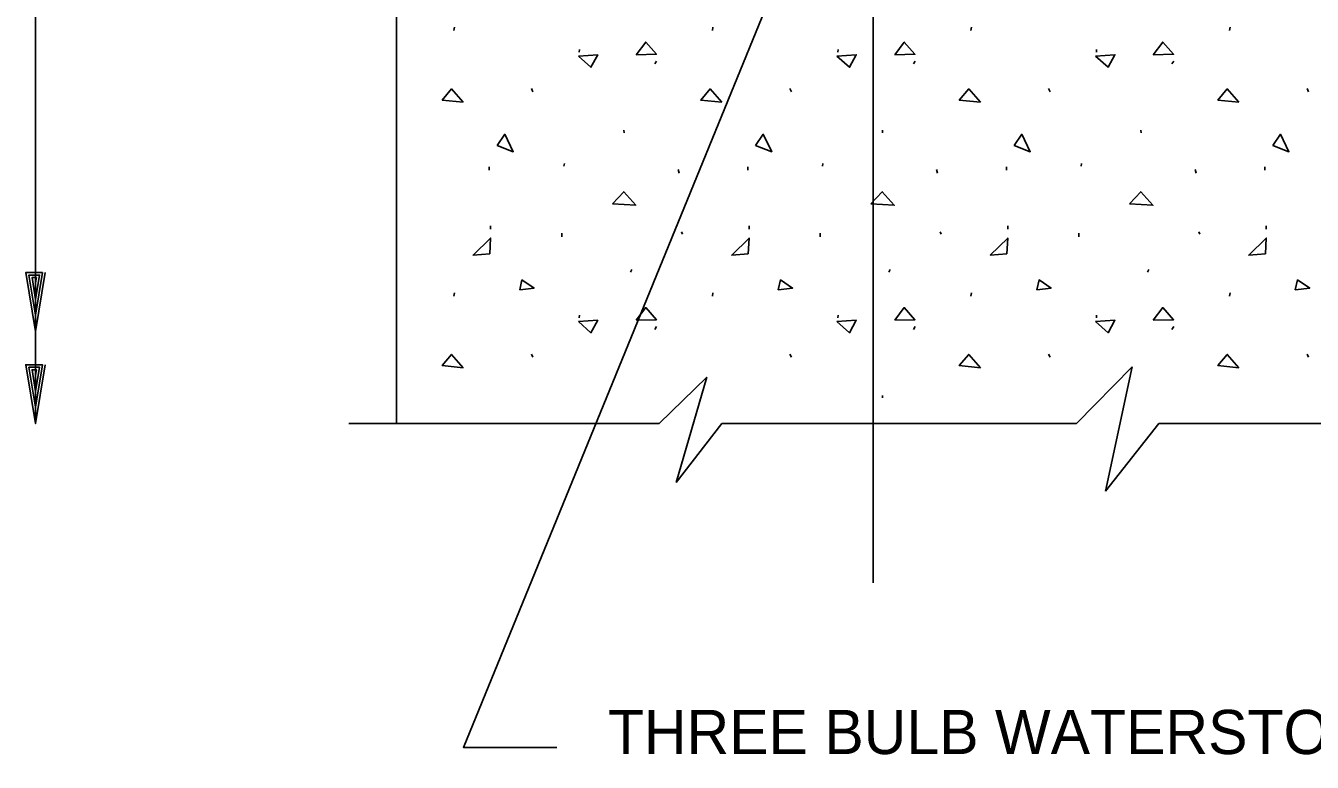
# Model space of a CAD drawing. Extents: x 44743.44 to 44747.1, y 44738.46 to 44741.29.
# Drawn here: x 44745.0695 to 44745.4095, y 44739.0153 to 44739.2099 of the extents above; entities that cross this region are included whole.
import ezdxf

# ---------------------------------------------------------------- set-up
doc = ezdxf.new("R2010")
doc.units = 0
for name, color, linetype in [('Level 1', 7, 'Continuous'), ('Level 10', 7, 'Continuous'), ('Level 2', 7, 'Continuous'), ('Level 8', 7, 'Continuous'), ('S-ANNO-TEXT', 7, 'Continuous')]:
    doc.layers.add(name, color=color, linetype=linetype)

msp = doc.modelspace()

# ---------------------------------------------------------------- linework, layer by layer
at = {"layer": 'Level 1'}
for p, q in [((44745.29347, 44739.69833), (44745.29347, 44739.06275)), ((44745.07206, 44739.10476), (44745.07206, 44739.35544)), ((44745.06947, 44739.14467), (44745.06947, 44739.14467)), ((44745.07389, 44739.14467), (44745.07389, 44739.14467)), ((44745.07464, 44739.14467), (44745.07464, 44739.14467)), ((44745.07031, 44739.14401), (44745.07031, 44739.14401)), ((44745.07114, 44739.14334), (44745.07114, 44739.14334)), ((44745.07206, 44739.14192), (44745.07206, 44739.14192)), ((44745.07231, 44739.14334), (44745.07231, 44739.14334)), ((44745.07314, 44739.14401), (44745.07314, 44739.14401)), ((44745.23686, 44739.10476), (44745.2495, 44739.11704)), ((44745.2495, 44739.11704), (44745.24135, 44739.08919)), ((44745.34716, 44739.10476), (44745.36187, 44739.1198)), ((44745.36187, 44739.1198), (44745.35486, 44739.08694)), ((44745.07206, 44739.10909), (44745.07206, 44739.10909)), ((44745.07206, 44739.10476), (44745.07206, 44739.10476)), ((44745.15487, 44739.10476), (44745.23686, 44739.10476)), ((44745.24135, 44739.08919), (44745.25345, 44739.10476)), ((44745.25345, 44739.10476), (44745.34716, 44739.10476)), ((44745.35486, 44739.08694), (44745.36897, 44739.10476)), ((44745.36897, 44739.10476), (44745.43132, 44739.10476))]:
    msp.add_line(p, q, dxfattribs=at)
for points in [[(44745.07464, 44739.14467), (44745.07206, 44739.12909), (44745.06947, 44739.14467), (44745.07389, 44739.14467), (44745.07206, 44739.13342), (44745.07031, 44739.14401), (44745.07314, 44739.14401), (44745.07206, 44739.13759), (44745.07114, 44739.14334), (44745.07231, 44739.14334), (44745.07206, 44739.14192)], [(44745.07464, 44739.12034), (44745.07206, 44739.10476), (44745.06947, 44739.12034), (44745.07389, 44739.12034), (44745.07206, 44739.10909), (44745.07031, 44739.11967), (44745.07314, 44739.11967), (44745.07206, 44739.11326), (44745.07114, 44739.11901), (44745.07231, 44739.11901), (44745.07206, 44739.11759)], [(44745.29592, 44739.11162), (44745.29588, 44739.11218)]]:
    msp.add_lwpolyline(points, dxfattribs=at)
at = {"layer": 'Level 10'}
msp.add_line((44745.16748, 44739.10476), (44745.16748, 44739.33461), dxfattribs=at)
at = {"layer": 'Level 2'}
msp.add_lwpolyline([(44745.28545, 44739.26441), (44745.18516, 44739.01925), (44745.20985, 44739.01925)], dxfattribs=at)
at = {"layer": 'Level 8'}
for p, q in [((44745.18263, 44739.2086), (44745.18277, 44739.20951)), ((44745.25096, 44739.2086), (44745.25111, 44739.20951)), ((44745.3193, 44739.2086), (44745.31944, 44739.20951)), ((44745.38763, 44739.2086), (44745.38777, 44739.20951)), ((44745.21577, 44739.20289), (44745.21584, 44739.20358)), ((44745.28411, 44739.20289), (44745.28417, 44739.20358)), ((44745.35244, 44739.20289), (44745.3525, 44739.20358)), ((44745.23573, 44739.19977), (44745.2362, 44739.20055)), ((44745.30407, 44739.19977), (44745.30454, 44739.20055)), ((44745.3724, 44739.19977), (44745.37287, 44739.20055)), ((44745.20354, 44739.19245), (44745.20312, 44739.19328)), ((44745.27187, 44739.19245), (44745.27145, 44739.19328)), ((44745.3402, 44739.19245), (44745.33979, 44739.19328)), ((44745.40854, 44739.19245), (44745.40812, 44739.19328)), ((44745.22761, 44739.18156), (44745.22755, 44739.18233)), ((44745.29594, 44739.18156), (44745.29588, 44739.18233)), ((44745.36427, 44739.18156), (44745.36421, 44739.18233)), ((44745.192, 44739.17168), (44745.192, 44739.17262)), ((44745.21171, 44739.1728), (44745.21184, 44739.1735)), ((44745.24215, 44739.17093), (44745.24189, 44739.17187)), ((44745.26034, 44739.17168), (44745.26034, 44739.17262)), ((44745.28005, 44739.1728), (44745.28017, 44739.1735)), ((44745.31048, 44739.17093), (44745.31022, 44739.17187)), ((44745.32867, 44739.17168), (44745.32867, 44739.17262)), ((44745.34838, 44739.1728), (44745.3485, 44739.1735)), ((44745.37882, 44739.17093), (44745.37856, 44739.17187)), ((44745.397, 44739.17168), (44745.397, 44739.17262)), ((44745.19234, 44739.15614), (44745.19234, 44739.15702)), ((44745.21113, 44739.15412), (44745.21113, 44739.15506)), ((44745.24309, 44739.15477), (44745.24283, 44739.15543)), ((44745.26067, 44739.15614), (44745.26067, 44739.15702)), ((44745.27946, 44739.15412), (44745.27946, 44739.15506)), ((44745.31142, 44739.15477), (44745.31116, 44739.15543)), ((44745.329, 44739.15614), (44745.329, 44739.15702)), ((44745.3478, 44739.15412), (44745.3478, 44739.15506)), ((44745.37975, 44739.15477), (44745.37949, 44739.15543)), ((44745.39734, 44739.15614), (44745.39734, 44739.15702)), ((44745.22927, 44739.14475), (44745.22962, 44739.14548)), ((44745.29761, 44739.14475), (44745.29795, 44739.14548)), ((44745.36594, 44739.14475), (44745.36629, 44739.14548)), ((44745.18263, 44739.13845), (44745.18277, 44739.13936)), ((44745.25096, 44739.13845), (44745.25111, 44739.13936)), ((44745.3193, 44739.13845), (44745.31944, 44739.13936)), ((44745.38763, 44739.13845), (44745.38777, 44739.13936)), ((44745.21577, 44739.13275), (44745.21584, 44739.13343)), ((44745.28411, 44739.13275), (44745.28417, 44739.13343)), ((44745.35244, 44739.13275), (44745.3525, 44739.13343)), ((44745.23573, 44739.12962), (44745.2362, 44739.1304)), ((44745.30407, 44739.12962), (44745.30454, 44739.1304)), ((44745.3724, 44739.12962), (44745.37287, 44739.1304)), ((44745.20354, 44739.12231), (44745.20312, 44739.12313)), ((44745.27187, 44739.12231), (44745.27145, 44739.12313)), ((44745.3402, 44739.12231), (44745.33979, 44739.12313)), ((44745.40854, 44739.12231), (44745.40812, 44739.12313))]:
    msp.add_line(p, q, dxfattribs=at)
for points in [[(44745.23083, 44739.20223), (44745.23334, 44739.20557), (44745.23617, 44739.20236)], [(44745.29916, 44739.20223), (44745.30167, 44739.20557), (44745.3045, 44739.20236)], [(44745.36749, 44739.20223), (44745.37, 44739.20557), (44745.37284, 44739.20236)], [(44745.21554, 44739.20187), (44745.21887, 44739.1989), (44745.22065, 44739.20223)], [(44745.28387, 44739.20187), (44745.2872, 44739.1989), (44745.28898, 44739.20223)], [(44745.3522, 44739.20187), (44745.35554, 44739.1989), (44745.35732, 44739.20223)], [(44745.18512, 44739.18964), (44745.18202, 44739.1932), (44745.17954, 44739.19025)], [(44745.25345, 44739.18964), (44745.25036, 44739.1932), (44745.24787, 44739.19025)], [(44745.32179, 44739.18964), (44745.31869, 44739.1932), (44745.3162, 44739.19025)], [(44745.39012, 44739.18964), (44745.38702, 44739.1932), (44745.38454, 44739.19025)], [(44745.19404, 44739.17825), (44745.19831, 44739.17659), (44745.19606, 44739.1812)], [(44745.26237, 44739.17825), (44745.26664, 44739.17659), (44745.26439, 44739.1812)], [(44745.3307, 44739.17825), (44745.33497, 44739.17659), (44745.33272, 44739.1812)], [(44745.39904, 44739.17825), (44745.40331, 44739.17659), (44745.40106, 44739.1812)], [(44745.22454, 44739.1628), (44745.22751, 44739.16602), (44745.2307, 44739.16245)], [(44745.29287, 44739.1628), (44745.29585, 44739.16602), (44745.29904, 44739.16245)], [(44745.3612, 44739.1628), (44745.36418, 44739.16602), (44745.36737, 44739.16245)], [(44745.1921, 44739.14962), (44745.19234, 44739.1538), (44745.18771, 44739.14928)], [(44745.26043, 44739.14962), (44745.26067, 44739.1538), (44745.25605, 44739.14928)], [(44745.32876, 44739.14962), (44745.329, 44739.1538), (44745.32438, 44739.14928)], [(44745.3971, 44739.14962), (44745.39734, 44739.1538), (44745.39271, 44739.14928)], [(44745.20002, 44739.14009), (44745.20382, 44739.14058), (44745.20063, 44739.14271)], [(44745.26836, 44739.14009), (44745.27215, 44739.14058), (44745.26896, 44739.14271)], [(44745.33669, 44739.14009), (44745.34048, 44739.14058), (44745.3373, 44739.14271)], [(44745.40502, 44739.14009), (44745.40882, 44739.14058), (44745.40563, 44739.14271)], [(44745.23083, 44739.13209), (44745.23334, 44739.13542), (44745.23617, 44739.13221)], [(44745.29916, 44739.13209), (44745.30167, 44739.13542), (44745.3045, 44739.13221)], [(44745.36749, 44739.13209), (44745.37, 44739.13542), (44745.37284, 44739.13221)], [(44745.21554, 44739.13172), (44745.21887, 44739.12876), (44745.22065, 44739.13209)], [(44745.28387, 44739.13172), (44745.2872, 44739.12876), (44745.28898, 44739.13209)], [(44745.3522, 44739.13172), (44745.35554, 44739.12876), (44745.35732, 44739.13209)], [(44745.18512, 44739.1195), (44745.18202, 44739.12306), (44745.17954, 44739.1201)], [(44745.32179, 44739.1195), (44745.31869, 44739.12306), (44745.3162, 44739.1201)], [(44745.39012, 44739.1195), (44745.38702, 44739.12306), (44745.38454, 44739.1201)]]:
    msp.add_lwpolyline(points, close=True, dxfattribs=at)

# ---------------------------------------------------------------- texts
at = {"layer": 'S-ANNO-TEXT'}
msp.add_text('THREE BULB WATERSTOP,', height=0.0116667, dxfattribs=at).set_placement((44745.22334, 44739.01748))

doc.saveas('drawing.dxf')
